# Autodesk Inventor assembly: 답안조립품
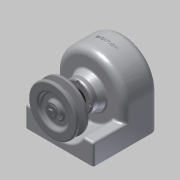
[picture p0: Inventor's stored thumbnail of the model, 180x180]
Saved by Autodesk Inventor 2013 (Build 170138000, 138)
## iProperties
Created: 2015-02
Part Number: 답안조립품
Document SubType Name: Assembly
Designer: Administrator
Author: Administrator
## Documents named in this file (14)
- C:\Users\Administrator\Desktop\450216V1017\답안조립품.iam
- C:\Users\Administrator\Desktop\450216V1017\본체.ipt
- C:\Users\Administrator\Desktop\450216V1017\베어링 6001.ipt
- C:\Users\Administrator\Desktop\450216V1017\축커버.ipt
- C:\Users\Administrator\Desktop\450216V1017\오일실.ipt
- C:\Users\Administrator\Desktop\450216V1017\M3x0.5.ipt
- C:\Users\Administrator\Desktop\450216V1017\축.ipt
- C:\Users\Administrator\Desktop\450216V1017\키4x4.ipt
- C:\Users\Administrator\Desktop\450216V1017\키5x5.ipt
- C:\Users\Administrator\Desktop\450216V1017\스퍼기어.ipt
- C:\Users\Administrator\Desktop\450216V1017\V-벨트풀리.ipt
- C:\Users\Administrator\Desktop\450216V1017\M5x0.8.ipt
- M5x0.8.ipt
- C:\Users\Administrator\Desktop\450216V1017\와샤.ipt
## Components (6 placed, 3 different names)
1. V-벨트풀리:1 — 각도:4
2. M5x0.8:1 — 각도:5
3. M3x0.5:1
4. M3x0.5:2
5. M3x0.5:3
6. M3x0.5:4
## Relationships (2: Angle 2)
- 각도:4 [Angle]: V-벨트풀리:1
- 각도:5 [Angle]: M5x0.8:1
